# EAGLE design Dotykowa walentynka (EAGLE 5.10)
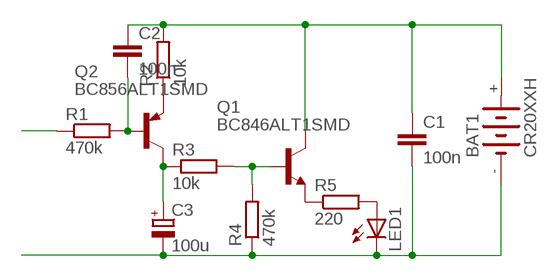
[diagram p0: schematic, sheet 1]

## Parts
BAT1  CR20XXH  [CR2025H]
C1  100n  C-EUC0805  [C0805]
C2  100n  C-EUC0805  [C0805]
C3  100u  CPOL-EUE2,5-6E  [E2,5-6E]
LED1  LEDCHIP-LED0805  [CHIP-LED0805]
Q1  BC846ALT1SMD  [SOT23]
Q2  BC856ALT1SMD  [SOT23-BEC]
R1  470k  R-EU_M0805  [M0805]
R2  10k  R-EU_M0805  [M0805]
R3  10k  R-EU_M0805  [M0805]
R4  470k  R-EU_M0805  [M0805]
R5  220  R-EU_M0805  [M0805]

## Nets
GND: BAT1.- C1.2 C3.- LED1.C R4.1
N$1: C2.2 Q2.B R1.2
N$2: BAT1.+ C1.1 C2.1 Q1.3(C) R2.2
N$4: Q2.E R2.1
N$6: C3.+ Q2.C R3.1
N$7: Q1.1(B) R3.2 R4.2
N$9: Q1.2(E) R5.1
N$10: LED1.A R5.2
SG: R1.1

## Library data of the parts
BAT1 = battery:CR20XXH: LI BATTERY
C1 C2 = rcl:C-EU: CAPACITOR, European symbol
C3 = rcl:CPOL-EU: POLARIZED CAPACITOR, European symbol
LED1 = led:LED: LED
Q1 = transistor-npn:BC846*: NPN Transistor
Q2 = transistor-pnp:BC856*: PNP Transistror
R1-R5 = rcl:R-EU_: RESISTOR, European symbol

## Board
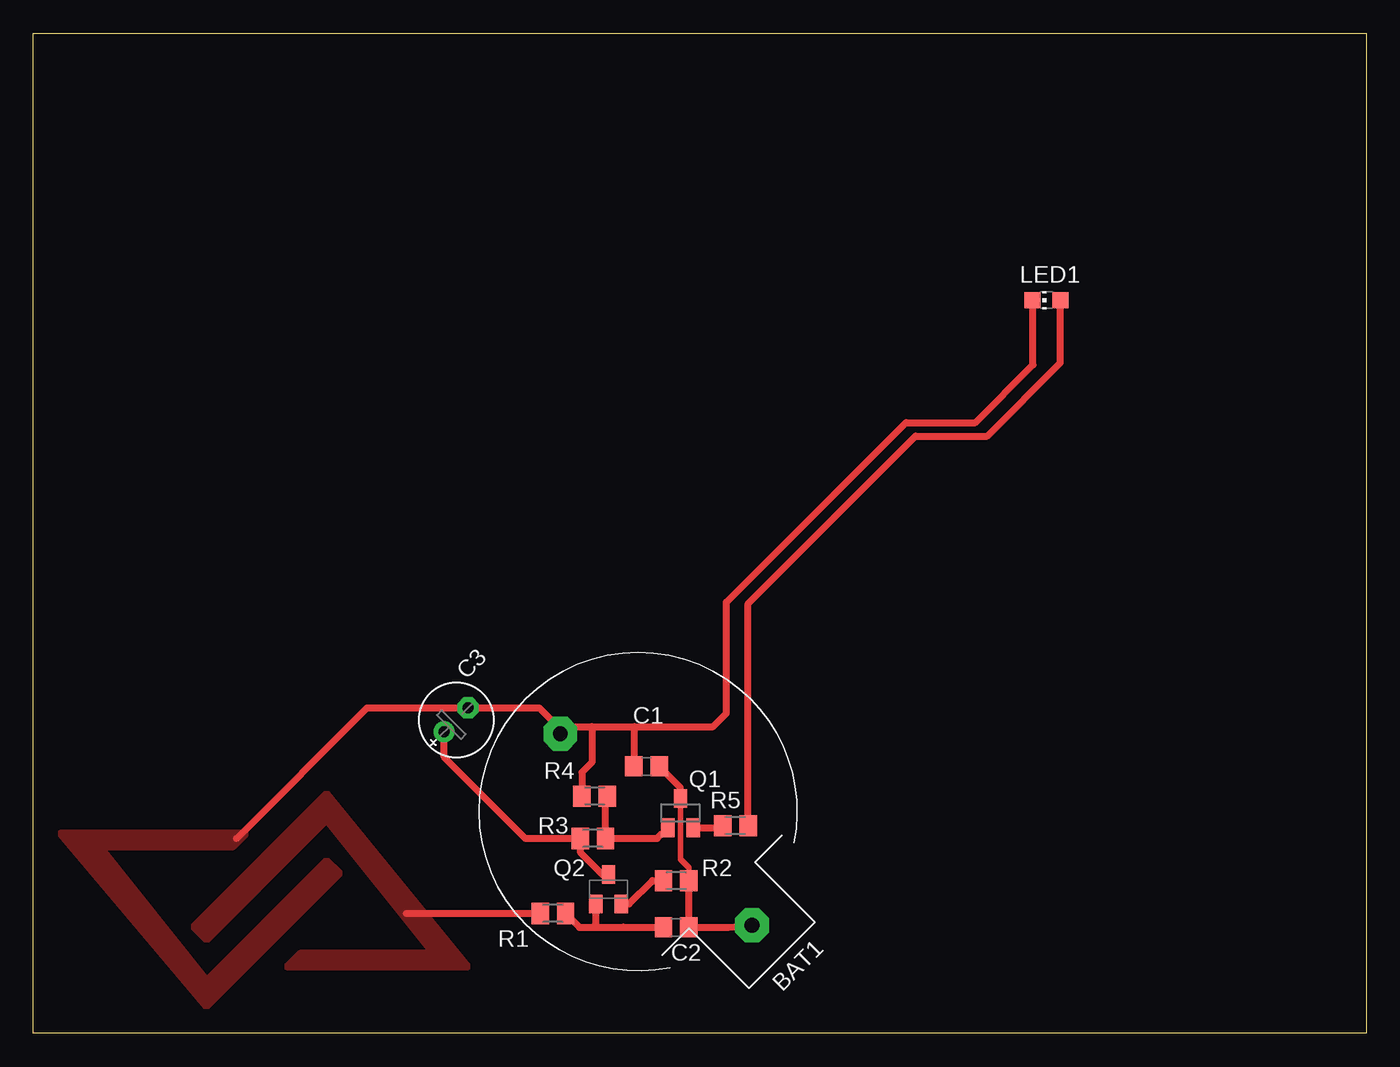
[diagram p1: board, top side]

Size 100 x 75 mm. Coordinates in mm from the lower left corner, seen from the top.
Outline: 0,0 0,75 100,75 100,0 0,0
Copper layers (1*16): Top 0.035mm / dielectric 1.5mm / Bottom 0.035mm
Design rules "default *": minimum track width 15mil, minimum drill 24mil, track to track 8mil, track to pad 8mil, pad to pad 8mil, via to via 8mil, smd to smd 8mil, copper to edge 5mil, drill to drill 8mil, minimum pad ring 10mil, minimum via ring 8mil, stop-mask expansion 4mil, vias tented up to drill 0mil, thermal gap 10mil

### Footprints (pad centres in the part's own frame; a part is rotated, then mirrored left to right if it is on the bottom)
CR2025H = drill 1.118 pad 2.54 octagon: + 0,12.065; - 0,-8.255
C0805 = smd 1.3 x 1.5: 1 -0.95,0; 2 0.95,0
E2,5-6E = drill 0.813 pad 1.575 round: + -1.27,0 | drill 0.813 pad 1.575 octagon: - 1.27,0
CHIP-LED0805 = smd 1.2 x 1.2: A 0,-1.05; C 0,1.05
SOT23 = smd 1 x 1.4: 1 -0.95,-1.1; 2 0.95,-1.1; 3 0,1.1
SOT23-BEC = smd 1 x 1.4: B -0.95,-1.1; C 0,1.1; E 0.95,-1.1
M0805 = smd 1.3 x 1.6: 1 -0.95,0; 2 0.95,0

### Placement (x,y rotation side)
BAT1  CR2032  [CR2025H]  45.38,16.63 225 top
C1  46.01,20.02 180 top
C2  48.23,7.95 180 top
C3  31.72,23.51 45 top
LED1  76,55 90 top
Q1  BC846  [SOT23]  48.55,16.52 0 top
Q2  BC856  [SOT23-BEC]  43.15,10.81 0 top
R1  38.98,9 0 top
R2  48.23,11.45 0 top
R3  41.98,14.62 0 top
R4  42.11,17.79 0 top
R5  52.68,15.57 0 top

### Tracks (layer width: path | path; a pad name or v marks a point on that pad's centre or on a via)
GND
  Top 0.508: LED1.C 75,54.95 75,50.13 70.67,45.81 65.47,45.81 52,32.34 52,24 51,23 45.09,23 | 15.24,14.61 25.04,24.41 C3.- 37.96,24.41 39.37,23 | 39.37,23 41.91,23 | 41.91,23 45.09,23 | BAT1.- 39.54,22.83 39.37,23 | C1.2 45.06,22.98 45.09,23 | R4.1 41.16,19.57 41.91,20.32 41.91,23
  pour Top: 2,15 13,2 23,12 22,13 13,4 5,14 15,14 16,15
N$1
  Top 0.508: 44.26,7.95 C2.2 | 44.26,7.95 44.25,7.96 | 42,7.95 40.98,7.95 R1.2 | 42,7.95 44.26,7.95 | Q2.B 42.2,8.15 42,7.95
N$2
  Top 0.406: Q1.3 48.55,13.04 49.18,12.41 R2.2
  Top 0.508: R2.2 C2.1 52.15,7.95 BAT1.+ | Q1.3 48.55,18.43 C1.1
N$4
  Top 0.508: 46.97,11.76 R2.1 46.45,11.45 44.71,9.71 Q2.E
N$6
  Top 0.508: Q2.C 42.7,11.91 41.03,13.58 R3.1 36.91,14.62 30.82,20.71 C3.+
N$7
  Top 0.508: Q1.1 46.8,14.62 R3.2 42.93,17.66 R4.2
N$9
  Top 0.508: Q1.2 51.58,15.43 R5.1
N$10
  Top 0.508: R5.2 53.63,32.23 66.19,44.79 71.56,44.79 77.05,50.28 LED1.A
SG
  Top 0.508: 28,9 R1.1
  pour Top: 19,5 32.63,5 22,18 12,8 13,7 22,16 30,6 20,6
